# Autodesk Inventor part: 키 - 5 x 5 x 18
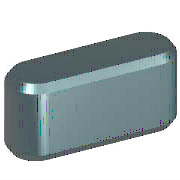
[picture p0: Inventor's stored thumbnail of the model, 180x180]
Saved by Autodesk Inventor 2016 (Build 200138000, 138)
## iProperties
Created: 2012-02
Part Number: 키 - 5 x 5 x 18
Material: 강철, 연강
Description: 키 및 해당 키홈
Document SubType Name: Modeling
Standard: KS B 1311
Designer: mduedu
Standards Organization: KS
Language: ko-KR
Size Designation: 5 x 5 x 18
Categories: <MemberInstance><Categories><Category DisplayName="샤프트 부품" InternalName="7f7aeb1f-a693-4053-b835-cee3144e0d98" Mnemonic="SHFT"><Category DisplayName="키" Interna
Density: 1 g/cm^3
Appearance: 매끄러움 - 노란색
IsCustomPart: 1
Author: mduedu
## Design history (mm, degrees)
workplane "Work Plane1"
workplane "Work Plane2"
sketch "스케치1"
  geometry: L1 (2.5, 2.5)-(15.5, 2.5); L2 (15.5, -2.5)-(2.5, -2.5); L3 (0, 9.4)-(0, -7.4) reference; L4 (-5, 0)-(30, 0) reference; L5 (18, 0)-(18, 7); A1 r 2.5 centre (2.5, 0) between (2.5, 2.5) and (2.5, -2.5); A2 r 2.5 centre (15.5, 0) between (15.5, -2.5) and (15.5, 2.5)
  constraints: 6 end point, 5 point on circle, 4 tangent, 3 point on line, 2 centre point, 1 horizontal, 1 parallel, 1 perpendicular
  dimensions: "d0" = 2.5 radius of A1 (= 0.5 x PB); "d13" = 2.5 radius of A2 (= 0.5 x PB); "d14" = 18 distance between parallel lines of L5 L3 (= NLG)
extrude "본체1" new body sketch "스케치1" taper "d3" = 0 deg; stored distance "d4" = 10
workplane "Work Plane3"
body "Solid1"
chamfer "모따기1" distance "d8" = 0.4 (= PHH); stored, may be unused: second distance "d9" = 0.4 (= PHH), angle "d15" = 45 deg
other parameters: "d1" = -3 (= -PNT), "d2" = 2 (= PH - PNT), "NLG" = 18 [user parameter; used in 3 equation terms], "PB" = 5 [user parameter; used in 2 equation terms], "PNT" = 3 [user parameter; used in 2 equation terms], "PH" = 5 [user parameter; used in 1 equation term], "PHH" = 0.4 [user parameter; used in 2 equation terms], "d10" = 0, "d16" = 0, "d17" = 0, "d18" = 0, "WDMIN" = 12 [user parameter], "PLB2" = 18 (= NLG) [user parameter], "WDMAX" = 17 [user parameter], "PLB1" = 18 (= NLG) [user parameter], "RR" = 0.16 [user parameter], "PUEB" = 2.3 [user parameter]
